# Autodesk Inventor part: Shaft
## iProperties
Shininess: 20.0
Length Units: 11269
Angle Units: 11279
Time Units: 11290
Mass Units: 11283
Length Display Precision: 3
Angle Display Precision: 2
Created: 2002-01
Part Number: Shaft
Document SubType Name: Modeling
Designer: ***
Density: 0.0
Volumn: 0.0
Area: 0.0
PropertySet Name: Model Information
Control State: 0
Master: False
Checked Out: False
Author: ***
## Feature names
1. Revolution1
2. Extrusion1
3. Extrusion2
4. Hole1
5. Chamfer1
